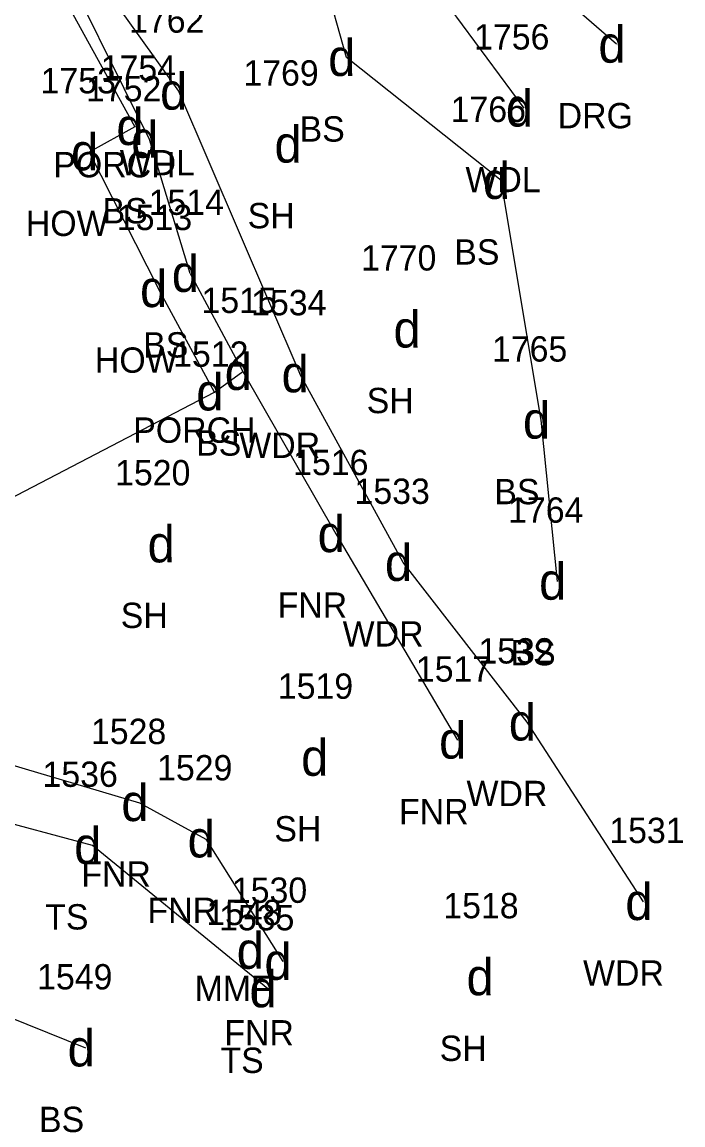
# Model space of a CAD drawing. Extents: x 461160 to 461373, y 202903 to 203086.
# Drawn here: x 461350.31 to 461370.15, y 202961.57 to 202994.66 of the extents above; entities that cross this region are included whole.
import ezdxf

# ---------------------------------------------------------------- set-up
doc = ezdxf.new("R2010")
doc.units = 0
for name, color, linetype in [('Level 11', 7, 'Continuous'), ('Level 12', 7, 'Continuous'), ('Level 13', 7, 'Continuous'), ('Level 14', 7, 'Continuous'), ('Level 46', 7, 'Continuous'), ('Level 47', 7, 'Continuous'), ('Level 48', 7, 'Continuous'), ('Level 49', 7, 'Continuous')]:
    doc.layers.add(name, color=color, linetype=linetype)

msp = doc.modelspace()

# ---------------------------------------------------------------- linework, layer by layer
at = {"layer": 'Level 11'}
msp.add_lwpolyline([(461368.16, 202993.988), (461361.614, 202999.669), (461352.956, 203006.007), (461341.424, 203009.197), (461337.518, 203007.355), (461337.431, 203004.112), (461337.186, 202997.424), (461334.068, 202989.63), (461330.234, 202984.513), (461326.916, 202981.421), (461323.296, 202985.661), (461325.835, 202988.474), (461328.575, 202993.98), (461329.756, 202998.988), (461329.989, 203003.994), (461337.431, 203004.112), (461329.989, 203003.994)], dxfattribs=at)
at = {"layer": 'Level 12'}
for points in [[(461344.281, 202988.129), (461340.027, 202985.73), (461335.779, 202983.392), (461339.702, 202978.527), (461342.84, 202975.899), (461349.186, 202972.612), (461353.842, 202971.233), (461355.83, 202970.143), (461358.135, 202966.469)], [(461356.092, 202983.553), (461356.944, 202984.167), (461359.734, 202979.302), (461363.379, 202973.107)]]:
    msp.add_lwpolyline(points, dxfattribs=at)
at = {"layer": 'Level 13'}
for points in [[(461344.281, 202988.129), (461341.364, 202993.658), (461347.97, 202997.141), (461350.021, 202998.196), (461353.693, 202991.517), (461352.33, 202990.757), (461354.403, 202986.654)], [(461344.281, 202988.129), (461348.72, 202979.72), (461356.092, 202983.553), (461354.403, 202986.654)]]:
    msp.add_lwpolyline(points, dxfattribs=at)
at = {"layer": 'Level 14'}
for points in [[(461365.381, 202992.072), (461359.835, 202999.587), (461349.026, 203006.664), (461347.903, 203004.737), (461349.013, 203000.332), (461350.745, 202998.529), (461355.004, 202992.578), (461358.651, 202984.097)], [(461368.969, 202968.263), (461365.471, 202973.65), (461361.753, 202978.439), (461358.651, 202984.097)]]:
    msp.add_lwpolyline(points, dxfattribs=at)
at = {"layer": 'Level 48'}
for points in [[(461366.381, 202977.875), (461365.896, 202982.709), (461364.694, 202989.899), (461360.051, 202993.589), (461358.714, 202998.363)], [(461366.381, 202977.875), (461365.896, 202982.709), (461364.694, 202989.899), (461360.051, 202993.589), (461358.714, 202998.363)], [(461355.356, 202987.111), (461354.135, 202991.134), (461351.105, 202997.24)], [(461355.356, 202987.111), (461354.135, 202991.134), (461351.105, 202997.24)], [(461355.356, 202987.111), (461356.944, 202984.167)], [(461355.356, 202987.111), (461356.944, 202984.167)], [(461357.687, 202965.645), (461352.427, 202969.949), (461345.877, 202971.711), (461340.176, 202976.089), (461332.316, 202982.931), (461327.452, 202981.402), (461327.836, 202980.984)], [(461357.687, 202965.645), (461352.427, 202969.949), (461345.877, 202971.711), (461340.176, 202976.089), (461332.316, 202982.931), (461327.452, 202981.402), (461327.836, 202980.984)], [(461352.229, 202963.871), (461345.84, 202966.444), (461339.521, 202971.322), (461334.79, 202974.771), (461330.961, 202978.713), (461326.896, 202978.498)], [(461352.229, 202963.871), (461345.84, 202966.444), (461339.521, 202971.322), (461334.79, 202974.771), (461330.961, 202978.713), (461326.896, 202978.498)]]:
    msp.add_lwpolyline(points, dxfattribs=at)

# ---------------------------------------------------------------- texts
at = {"layer": 'Level 46'}
for s, p in [(' DRG  ', (461366.108, 202991.468)), (' BS  ', (461358.361, 202991.069)), (' WDL  ', (461352.961, 202990.058)), (' PORCH  ', (461350.968, 202989.997)), (' WDL  ', (461363.338, 202989.552)), (' BS  ', (461352.445, 202988.614)), (' SH  ', (461356.802, 202988.469)), (' HOW  ', (461350.143, 202988.237)), (' BS  ', (461363.004, 202987.379)), (' BS  ', (461353.666, 202984.591)), (' HOW  ', (461352.216, 202984.134)), (' SH  ', (461360.375, 202982.921)), (' PORCH  ', (461353.367, 202982.033)), (' BS  ', (461355.254, 202981.647)), (' WDR  ', (461356.551, 202981.577)), (' BS  ', (461364.206, 202980.189)), (' FNR  ', (461357.7, 202976.782)), (' SH  ', (461352.993, 202976.475)), (' WDR  ', (461359.653, 202975.919)), (' BS  ', (461364.691, 202975.355)), (' WDR  ', (461363.371, 202971.13)), (' FNR  ', (461361.345, 202970.587)), (' SH  ', (461357.603, 202970.071)), (' FNR  ', (461351.808, 202968.713)), (' FNR  ', (461353.796, 202967.623)), (' TS  ', (461350.725, 202967.429)), (' WDR  ', (461366.869, 202965.743)), (' MMF  ', (461355.21, 202965.28)), (' FNR  ', (461356.101, 202963.949)), (' SH  ', (461362.566, 202963.486)), (' TS  ', (461355.985, 202963.125)), (' BS  ', (461350.539, 202961.351))]:
    msp.add_text(s, height=0.76, dxfattribs=at).set_placement(p)
at = {"layer": 'Level 47'}
for p in [(461367.61, 202993.438), (461359.501, 202993.039), (461354.454, 202992.028), (461364.831, 202991.522), (461353.143, 202990.967), (461353.585, 202990.584), (461357.888, 202990.439), (461351.78, 202990.207), (461364.144, 202989.349), (461354.806, 202986.561), (461353.853, 202986.104), (461361.461, 202984.891), (461356.394, 202983.617), (461358.101, 202983.547), (461355.542, 202983.003), (461365.346, 202982.159), (461359.184, 202978.752), (461354.079, 202978.445), (461361.203, 202977.889), (461365.831, 202977.325), (461364.921, 202973.1), (461362.829, 202972.557), (461358.689, 202972.041), (461353.292, 202970.683), (461355.28, 202969.593), (461351.877, 202969.399), (461368.419, 202967.713), (461356.754, 202966.25), (461357.585, 202965.919), (461363.652, 202965.456), (461357.137, 202965.095), (461351.679, 202963.321)]:
    msp.add_text('d', height=1.1, dxfattribs=at).set_placement(p)
at = {"layer": 'Level 49'}
for s, p in [(' 1762 ', (461353.242, 202994.338)), (' 1756 ', (461363.598, 202993.832)), (' 1754 ', (461352.391, 202992.894)), (' 1769 ', (461356.673, 202992.749)), (' 1753 ', (461350.586, 202992.517)), (' 1752 ', (461351.949, 202992.277)), (' 1766 ', (461362.893, 202991.659)), (' 1514 ', (461353.828, 202988.871)), (' 1513 ', (461352.875, 202988.414)), (' 1770 ', (461360.204, 202987.201)), (' 1515 ', (461355.416, 202985.927)), (' 1534 ', (461356.907, 202985.857)), (' 1765 ', (461364.134, 202984.469)), (' 1512 ', (461354.564, 202984.313)), (' 1520 ', (461352.822, 202980.755)), (' 1516 ', (461358.167, 202981.062)), (' 1533 ', (461360.009, 202980.199)), (' 1764 ', (461364.619, 202979.635)), (' 1532 ', (461363.727, 202975.41)), (' 1517 ', (461361.851, 202974.867)), (' 1519 ', (461357.708, 202974.351)), (' 1528 ', (461352.098, 202972.993)), (' 1529 ', (461354.083, 202971.903)), (' 1536 ', (461350.644, 202971.709)), (' 1531 ', (461367.656, 202970.023)), (' 1530 ', (461356.328, 202968.229)), (' 1548 ', (461355.56, 202967.56)), (' 1518 ', (461362.674, 202967.766)), (' 1535 ', (461355.943, 202967.405)), (' 1549 ', (461350.482, 202965.631))]:
    msp.add_text(s, height=0.76, dxfattribs=at).set_placement(p)

doc.saveas('drawing.dxf')
